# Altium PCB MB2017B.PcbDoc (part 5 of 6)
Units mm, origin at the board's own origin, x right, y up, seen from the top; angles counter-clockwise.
Board outline 148.19 x 169.19 mm, 4 copper layers (Top Layer, Mid Layer 1, Mid Layer 2, Bottom Layer), stack 1.498 mm thick; 458 components, 208 nets, 1223 pads, 6162 vias.
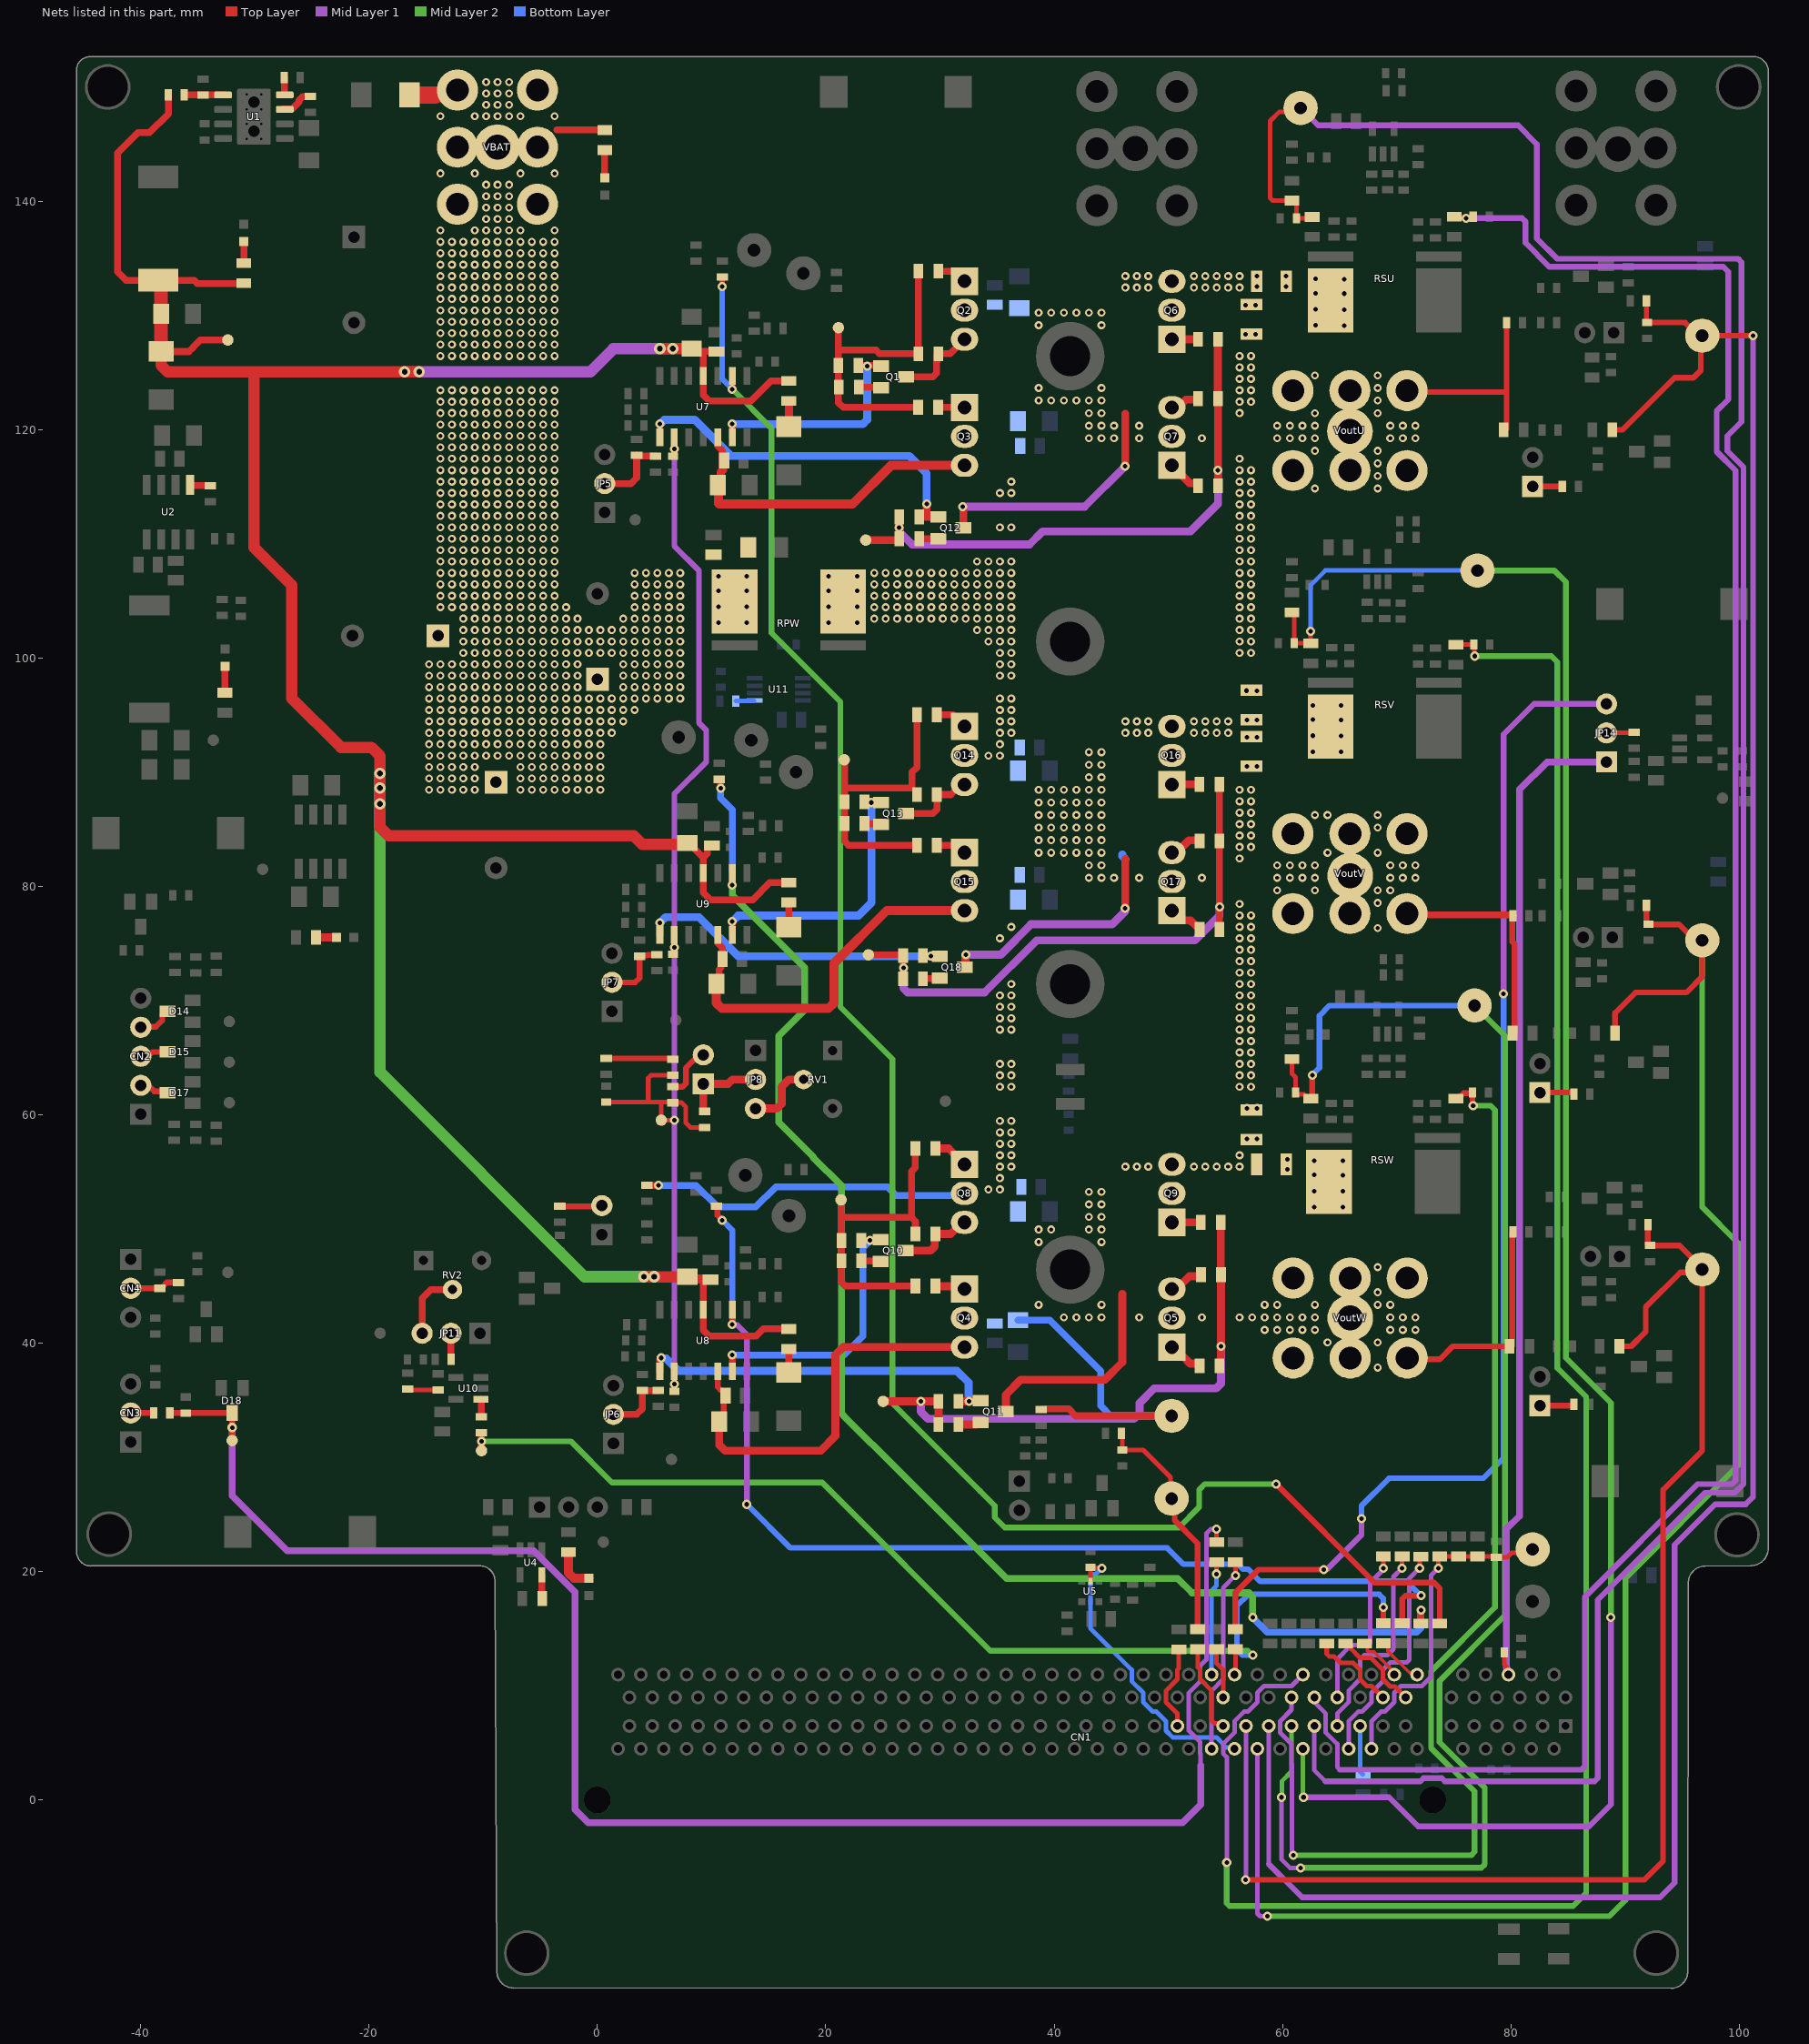
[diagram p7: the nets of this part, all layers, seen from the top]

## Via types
v1: diameter 0.7, hole 0.35, Top Layer to Bottom Layer, tented both sides, 5935 vias
v2: diameter 0.8, hole 0.4, Top Layer to Bottom Layer, tented both sides, 216 vias
v3: diameter 1, hole 0.5, Top Layer to Bottom Layer, tented both sides, 9 vias
v4: diameter 0.8, hole 0.4, Top Layer to Bottom Layer, 2 vias

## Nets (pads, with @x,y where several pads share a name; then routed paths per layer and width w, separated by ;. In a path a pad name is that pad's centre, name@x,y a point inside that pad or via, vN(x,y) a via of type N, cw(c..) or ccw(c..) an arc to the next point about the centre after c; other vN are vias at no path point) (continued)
NetCN1_A16: CN1.A16 Enable.1 R36.1 R39.1 R42.1 R44.2 | length 29
  Top Layer w0.4: v2(73.66,20.32) 73.66,21.223 R42.1@73.787,21.35 R39.1@75.438,21.35 R36.1@77.089,21.35 78.661,21.35 R44.2@78.74,21.271 79.691,21.271 80.068,21.648 81.592,21.648 Enable.1@81.915,21.971
  Mid Layer 1 w0.4: CN1.A16@67.8,4.5 67.8,6.914 68.636,7.75 68.964,7.75 69.8,8.586 69.8,9.414 70.386,10 72.214,10 73.025,10.811 73.025,19.685 v2(73.66,20.32)
NetCN1_A17: CN1.A17 R183.1 | length 4.4
  Bottom Layer w0.4: CN1.A17@66.8,6.5 66.8,2.483 67.025,2.258 R183.1@67.056,2.258
NetCN1_A18: CN1.A18 R43.1 | length 20.5
  Top Layer w0.4: v2(72.009,20.32) 72.009,21.209 R43.1@72.136,21.336
  Mid Layer 1 w0.4: CN1.A18@65.8,4.5 65.8,6.914 66.636,7.75 66.964,7.75 67.8,8.586 67.8,9.414 68.8,10.414 68.8,11.414 69.451,12.065 70.886,12.065 71.12,12.299 71.12,19.431 v2(72.009,20.32)
NetCN1_A19: CN1.A19 R45.1 | length 18.4
  Top Layer w0.4: v2(70.485,20.32) R45.1@70.485,21.35
  Mid Layer 1 w0.4: CN1.A19@64.8,6.5 64.8,7.586 65.8,8.586 65.8,9.586 66.8,10.586 66.8,11.414 66.8,12.317 67.183,12.7 69.215,12.7 69.723,13.208 69.723,19.558 v2(70.485,20.32)
NetCN1_A29: CN1.A29 R48.1 | length 8
  Top Layer w0.4: R48.1@52.578,13.222 52.578,11.636 52.8,11.414 52.8,10.586 53.8,9.586 53.8,6.965 54.034,6.731 54.353,6.731 54.584,6.5 CN1.A29@54.8,6.5
NetCN1_A30: CN1.A30 R50.1 | length 17.2
  Top Layer w0.4: v2(55.88,19.685) R50.1@55.88,20.842
  Mid Layer 1 w0.4: CN1.A30@53.8,4.5 53.8,9.586 54.8,10.586 54.8,18.605 v2(55.88,19.685)
NetCN1_A33: CN1.A33 R52.1 | length 7.6
  Top Layer w0.4: CN1.A33@50.8,6.5 50.8,7.586 49.8,8.586 49.8,9.586 50.8,10.586 50.8,11.414 50.927,11.541 R52.1@50.927,13.208
NetCN1_B12: CN1.B12 R33.2 | length 4.3
  Top Layer w0.3: R33.2@68.834,13.744 68.974,13.744 69.249,13.469 69.249,13.047 71.124,11.172 71.628,11.172 CN1.B12@71.8,11
NetCN1_B13: CN1.B13 R35.2 | length 7.8
  Top Layer w0.4: R35.2@65.532,13.73 65.757,13.73 65.982,13.505 65.982,13.28 66.816,12.446 67.768,12.446 68.8,11.414 68.8,10.586 69.433,9.953 69.847,9.953 CN1.B13@70.8,9
NetCN1_B14: CN1.B14 R38.2 | length 4.1
  Top Layer w0.3: R38.2@67.183,13.73 67.437,13.476 67.437,13.081 67.522,12.996 67.996,12.996 68.5,12.493 69.8,11.192 CN1.B14@69.8,11
NetCN1_B15: CN1.B15 R41.2 | length 7.9
  Top Layer w0.4: R41.2@63.881,13.73 63.881,12.807 64.115,12.573 64.54,12.573 65.091,12.023 66.191,12.023 66.8,11.414 66.8,10.586 67.386,10 67.8,10 CN1.B15@68.8,9
NetCN1_B19: CN1.B19 R46.2 | length 15.3
  Top Layer w0.4: CN1.B19@64.8,9 64.8,9.216 64.966,9.382 CN1.B19@64.966,9.4 ; v2(68.834,20.32) R46.2@68.834,21.35
  Mid Layer 1 w0.4: CN1.B19@64.8,9 64.8,12.349 66.04,13.589 67.457,13.589 67.691,13.823 67.691,19.05 68.634,19.993 68.634,20.012 68.834,20.212 v2(68.834,20.32)
NetCN1_B28: CN1.B28 R47.2 | length 2.3
  Top Layer w0.4: CN1.B28@55.8,11 55.88,11.08 R47.2@55.88,13.222
NetCN1_B29: CN1.B29 R49.2 | length 4.5
  Top Layer w0.4: R49.2@54.229,13.222 54.229,11.985 54.8,11.414 CN1.B29@54.8,9
NetCN1_B30: CN1.B30 R51.2 | length 10
  Top Layer w0.4: v2(54.229,19.812) R51.2@54.229,20.842
  Bottom Layer w0.4: CN1.B30@53.8,11 53.8,18.367 54.229,18.796 v2(54.229,19.812)
NetCN2_2: CN2.2 D17.3 | length 2.6
  Top Layer w0.5: CN2.2@-40.005,62.611 -39.747,62.353 -39.112,62.353 -38.833,62.074 -37.774,62.074 D17.3@-37.676,61.976
NetCN2_3: CN2.3 D15.3 | length 2.5
  Top Layer w0.5: CN2.3@-40.005,65.151 -39.747,65.409 -39.112,65.409 -38.989,65.532 D15.3@-37.676,65.532
NetCN2_4: CN2.4 D14.3 | length 3.2
  Top Layer w0.5: CN2.4@-40.005,67.691 -39.956,67.74 -38.686,67.74 -38.126,68.3 -38.126,68.838 -37.876,69.088 D14.3@-37.676,69.088
NetCN3_2: CN3.2 R160.1 | length 2
  Top Layer w0.5: CN3.2@-40.894,33.909 R160.1@-38.862,33.909
NetCN4_2: CN4.2 R173.1 R178.1 | length 4.4
  Top Layer w0.5: CN4.2@-40.894,44.831 R178.1@-38.354,44.831 -38.174,44.831 -38.104,44.901 -38.104,44.954 -37.719,45.339 R173.1@-36.703,45.339
NetD6_2: D6.2 R61.2 | length 2.3
  Top Layer w0.7: D6.2@16.764,120.298 R61.2@16.764,122.555
NetD7_2: D7.2 R91.2 | length 2
  Top Layer w0.6: D7.2@16.764,37.465 R91.2@16.764,39.511
NetD8_2: D8.2 R90.2 | length 2.2
  Top Layer w0.6: D8.2@16.764,76.454 R90.2@16.764,78.627
NetGHU_1: GHU.1 R59.2 R60.2 R62.1 R63.1 R64.2 | length 28.1
  Top Layer w0.6: GHU.1@21.105,128.967 21.105,127.127 ; R63.1@28.09,121.982 21.528,121.982 21.105,122.405 R59.2@21.105,125.665 21.105,127.127 ; R62.1@28.104,133.92 R64.2@28.104,126.681 24.703,126.681 24.384,127 21.232,127 21.105,127.127
NetGHV_1: GHV.1 R88.2 R89.2 R92.1 R93.1 R94.2 | length 26.1
  Top Layer w0.6: GHV.1@21.613,91.121 21.641,91.093 21.641,88.646 ; R93.1@27.977,83.628 21.992,83.628 21.641,83.979 R89.2@21.641,85.533 R88.2@21.641,87.438 21.641,88.646 ; R92.1@27.977,95.058 27.977,90.461 27.559,90.043 27.559,88.646 21.641,88.646
NetGHW_1: GHW.1 R65.1 R69.1 R75.1 R78.2 R86.2 | length 27.8
  Top Layer w0.6: GHW.1@21.336,52.578 21.336,51.054 ; R65.1@27.85,45.02 21.687,45.02 21.336,45.371 21.336,47.216 R78.2@21.364,47.244 R86.2@21.364,49.022 21.336,49.05 21.336,51.054 ; R69.1@27.85,49.592 27.85,50.703 27.499,51.054 ; R75.1@27.85,57.085 27.813,57.048 27.813,55.372 27.499,55.058 27.499,51.054 ; 21.336,51.054 27.499,51.054
NetGLU_1: GLU.1 R70.1 R71.1 R73.1 R83.2 R85.2 | length 50.9
  Top Layer w0.7: GLU.1@23.495,110.363 26.355,110.363 26.43,110.438 R85.2@26.43,110.49 v2(26.43,111.442) R83.2@26.43,112.395 ; R70.1@54.351,127.951 54.351,122.744 54.356,122.739 54.356,115.133 R71.1@54.365,115.124
  Mid Layer 1 w0.7: v2(26.43,111.442) 26.449,111.423 26.449,111.092 27.559,109.982 37.846,109.982 38.989,111.125 51.943,111.125 54.356,113.538 v2(54.356,116.459)
NetGLV_1: GLV.1 R97.1 R98.1 R100.1 R108.2 R109.2 | length 51
  Top Layer w0.6: GLV.1@23.729,74.037 26.706,74.037 R108.2@26.768,73.975 R109.2@26.768,71.943 ; R97.1@54.478,88.962 54.478,84.009 54.483,84.004 54.483,76.271 R98.1@54.492,76.262
  Mid Layer 1 w0.7: v2(26.797,72.898) 26.797,71.12 27.051,70.866 27.178,70.739 33.909,70.739 38.481,75.311 52.324,75.311 54.483,77.47 v2(54.483,78.232)
NetGLW_1: GLW.1 R66.1 R67.1 R76.1 R84.2 R87.2 | length 52
  Top Layer w0.7: GLW.1@25.019,34.925 v2(28.321,34.925) R87.2@29.873,34.925 29.873,32.907 R84.2@29.859,32.893 ; R66.1@54.492,38.035 54.567,38.11 54.567,38.485 54.605,38.523 54.605,39.612 54.61,39.617 54.61,46.031 54.605,46.036 R76.1@54.605,50.608
  Mid Layer 1 w0.7: v2(28.321,34.925) 28.321,34.036 28.956,33.401 46.99,33.401 47.498,33.909 47.498,34.798 48.768,36.068 54.2,36.068 54.61,36.478 v2(54.61,39.751)
NetJ1_1: J1.1 RSW.F2
  other v2: 65.278,51.943 62.783,51.957 65.278,53.34 62.783,53.354 65.278,54.737 62.783,54.751 60.452,55.245 65.278,56.007 62.783,56.021 60.452,56.134
NetJ2_1: J2.1 J5.1
  other v1: 56.247,100.484 57.247,100.484 56.247,101.484 57.247,101.484 56.247,102.484 57.247,102.484 56.247,103.484 57.247,103.484 56.247,104.484 57.247,104.484 56.247,105.484 57.247,105.484 56.247,106.484 57.247,106.484 56.247,107.484 57.247,107.484 56.247,108.484 57.247,108.484 56.247,109.484 57.247,109.484 56.247,110.484 57.247,110.484 56.247,111.484 57.247,111.484 56.247,112.484 57.247,112.484 56.247,113.484 57.247,113.484 56.247,114.484 57.247,114.484 56.247,115.484 57.247,115.484 56.247,116.484 57.247,116.484 56.247,117.484 56.247,121.484 56.247,122.484 57.247,122.484 56.247,123.484 57.247,123.484 56.247,124.484 57.247,124.484 56.247,125.484 57.247,125.484 56.247,126.484 57.247,126.484
  other v2: 57.785,97.155 56.859,97.175 56.769,128.397 57.658,128.397
NetJ3_2: J3.2 J6.1
  other v1: 56.247,62.484 57.247,62.484 56.247,63.484 57.247,63.484 56.247,64.484 57.247,64.484 56.247,65.484 57.247,65.484 56.247,66.484 57.247,66.484 56.247,67.484 57.247,67.484 56.247,68.484 57.247,68.484 56.247,69.484 57.247,69.484 56.247,70.484 57.247,70.484 56.247,71.484 57.247,71.484 56.247,72.484 57.247,72.484 56.247,73.484 57.247,73.484 56.247,74.484 57.247,74.484 56.247,75.484 57.247,75.484 56.247,76.484 57.247,76.484 56.247,77.484 57.247,77.484 56.247,78.484 56.247,82.484 56.247,83.484 57.247,83.484 56.247,84.484 57.247,84.484 56.247,85.484 57.247,85.484 56.247,86.484 57.247,86.484 56.247,87.484 57.247,87.484 56.247,88.484 57.247,88.484
  other v2: 56.896,60.579 57.785,60.579 56.896,90.551 57.785,90.551
NetJ4_1: J4.1 RSU.F2
  other v2: 65.405,129.159 62.91,129.173 65.405,130.556 62.91,130.57 65.405,131.953 62.91,131.967 60.325,132.588 65.405,133.223 62.91,133.237 60.325,133.477
NetJP2_1: JP2.1 R24.2 | length 2.6
  Top Layer w0.5: JP2.1@81.915,115.062 R24.2@84.517,115.062
NetJP3_1: JP3.1 R26.2 | length 3.1
  Top Layer w0.5: JP3.1@82.55,61.976 85.463,61.976 85.533,61.906 R26.2@85.533,61.849
NetJP4_1: JP4.1 R28.2 | length 3.1
  Top Layer w0.5: JP4.1@82.55,34.544 85.463,34.544 85.533,34.614 R28.2@85.533,34.671
NetJP5_2: JP5.2 R77.1 R81.2 | length 6.6
  Top Layer w0.6: JP5.2@0.635,115.316 2.921,115.316 3.429,115.824 R77.1@3.429,117.729 ; R77.1@3.429,117.791 R77.1@3.429,117.729 ; R81.2@5.08,117.729 R77.1@3.429,117.729
NetJP6_2: JP6.2 R79.1 R80.2 | length 5.7
  Top Layer w0.6: JP6.2@1.397,33.782 3.429,33.782 3.937,34.29 R79.1@3.937,35.876 5.331,35.876 R80.2@5.334,35.879
NetJP7_2: JP7.2 R102.1 R106.2 | length 6.1
  Top Layer w0.5: JP7.2@1.27,71.628 3.302,71.628 3.683,72.009 R102.1@3.683,73.911 3.753,73.981 4.385,73.981 4.445,74.041 R106.2@5.207,74.041
NetJP8_2: JP8.2 JP9.1 R110.2 | length 7.2
  Top Layer w0.7: R110.2@9.398,60.328 9.301,60.328 9.271,60.358 JP9.1@9.271,62.738 11.43,62.738 11.811,63.119 JP8.2@13.843,63.119
NetJP8_3: JP8.3 RV1.2 | length 6.1
  Top Layer w0.7: JP8.3@13.843,60.579 15.719,60.579 16.129,60.989 16.129,62.484 16.764,63.119 RV1.2@18.054,63.119
NetJP9_2: JP9.2 R111.1 | length 4.6
  Top Layer w0.5: R111.1@6.604,62.484 7.454,62.484 7.747,62.777 7.747,64.135 8.396,64.784 8.412,64.784 8.906,65.278 JP9.2@9.271,65.278
NetJP11_2: JP11.2 R119.2 | length 2.3
  Top Layer w0.6: R119.2@-12.827,38.608 JP11.2@-12.827,40.894
NetJP11_3: JP11.3 RV2.2 | length 6
  Top Layer w0.6: JP11.3@-15.367,40.894 -15.367,43.942 -14.585,44.724 RV2.2@-12.7,44.724
NetJP12_2: JP12.2 R125.2 | length 3.7
  Top Layer w0.5: R125.2@-3.302,52.008 0.319,52.008 JP12.2@0.381,52.07
NetJP14_2: JP14.2 R135.2 | length 2.4
  Top Layer w0.4: JP14.2@88.392,93.472 90.74,93.472 R135.2@90.805,93.537
NetLD1_1: LD1.1 R4.1 | length 1.9
  Top Layer w0.6: R4.1@-30.988,134.62 LD1.1@-30.988,136.525
NetLD2_1: LD2.1 R6.1 | length 2.4
  Top Layer w0.6: LD2.1@0.635,142.089 R6.1@0.635,144.526
NetLD3_1: LD3.1 R9.1 | length 2.3
  Top Layer w0.6: R9.1@-32.639,97 LD3.1@-32.639,99.314
NetLD4_1: LD4.1 R11.1 | length 1.8
  Top Layer w0.7: R11.1@-24.652,75.565 LD4.1@-22.86,75.565
NetLD5_1: LD5.1 R13.1 | length 3.8
  Top Layer w0.8: R13.1@-2.54,21.731 -2.54,19.9 -2.071,19.431 -0.774,19.431 LD5.1@-0.762,19.419
NetQ1_1: Q1.1 R59.1 U7.13 | length 19.8
  Top Layer w0.6: U7.13@11.811,119.347 v2(11.811,120.523) ; R59.1@22.855,125.665 24.765,125.665 Q1.1@24.831,125.599
  Bottom Layer w0.7: v2(11.811,120.523) 23.241,120.523 23.622,120.904 v2(23.622,125.603)
NetQ1_2: Q1.2 R60.1 | length 2
  Top Layer w0.6: R60.1@22.883,123.76 24.77,123.76 Q1.2@24.831,123.699
NetQ2_1: Q2.1 R62.2 | length 2.7
  Top Layer w0.6: R62.2@29.854,133.92 31.265,133.92 Q2.1@32.154,133.031
NetQ3_1: Q3.1 R63.2 | length 2.3
  Top Layer w0.6: R63.2@29.84,121.982 Q3.1@32.154,121.982
NetQ4_1: Q4.1 R65.2 | length 2.7
  Top Layer w0.6: Q4.1@31.9,45.02 Q4.1@32.154,44.766
  Top Layer w0.7: R65.2@29.6,45.02 Q4.1@31.9,45.02
NetQ5_1: Q5.1 R66.2 | length 3.2
  Top Layer w0.7: Q5.1@50.315,39.686 51.165,38.836 51.334,38.836 51.943,38.227 52.667,38.227 52.742,38.152 R66.2@52.742,38.035
NetQ6_1: Q6.1 R70.2 | length 2.3
  Top Layer w0.7: Q6.1@50.315,127.951 R70.2@52.601,127.951
NetQ7_1: Q7.1 R71.2 | length 3.1
  Top Layer w0.7: Q7.1@50.315,116.902 51.877,115.34 52.54,115.34 52.615,115.265 R71.2@52.615,115.124
NetQ8_1: Q8.1 R75.2 | length 3.1
  Top Layer w0.7: R75.2@29.6,57.085 30.757,57.085 Q8.1@32.154,55.688
NetQ9_1: Q9.1 R76.2 | length 2.5
  Top Layer w0.7: Q9.1@50.315,50.608 R76.2@52.855,50.608
NetQ10_1: Q10.1 R86.1 U8.13 | length 22.2
  Top Layer w0.6: U8.13@11.811,37.559 v2(11.811,38.989)
  Bottom Layer w0.6: v2(11.811,38.989) 21.59,38.989 23.241,40.64 23.241,48.387 v2(23.876,49.022)
NetQ10_2: Q10.2 R78.1 | length 1.7
  Top Layer w0.6: R78.1@23.114,47.244 23.145,47.213 24.777,47.213 Q10.2@24.808,47.183
NetQ11_1: Q11.1 R87.1 U8.8 | length 32.7
  Top Layer w0.6: U8.8@5.461,37.559 5.461,38.608 v2(5.588,38.735)
  Top Layer w0.7: R87.1@31.623,34.925 v2(32.567,34.925) 32.586,34.944 33.529,34.944 Q11.1@33.571,34.986
  Bottom Layer w0.6: v2(5.588,38.735) v2@5.626,38.697 ; v2@32.512,34.98 v2(32.567,34.925)
  Bottom Layer w0.7: v2@5.626,38.697 6.007,38.697 7.112,37.592 31.496,37.592 32.512,36.576 v2@32.512,34.98
NetQ11_2: Q11.2 R84.1 | length 2
  Top Layer w0.7: R84.1@31.609,32.893 33.178,32.893 33.371,33.086 Q11.2@33.571,33.086
NetQ12_1: Q12.1 R83.1 U7.8 | length 32.2
  Top Layer w0.5: U7.8@5.461,119.347 v2(5.461,120.523)
  Top Layer w0.7: R83.1@28.18,112.395 28.182,112.393 29.012,112.393 ; v2(28.829,113.538) 28.829,112.576 29.012,112.393 ; Q12.1@29.845,112.39 29.843,112.393 29.012,112.393
  Bottom Layer w0.7: v2(5.461,120.523) 5.488,120.523 5.869,120.904 8.509,120.904 11.684,117.729 27.305,117.729 28.829,116.205 v2(28.829,113.538)
NetQ12_2: Q12.2 R85.1 | length 1.7
  Top Layer w0.6: R85.1@28.18,110.49 Q12.2@29.845,110.49
NetQ13_1: Q13.1 R88.1 U9.13 | length 24.3
  Top Layer w0.6: U9.13@11.811,75.786 v2(11.811,76.962) ; R88.1@23.391,87.438 23.424,87.405 24.798,87.405 Q13.1@24.831,87.372
  Bottom Layer w0.7: v2(11.811,76.962) 12.319,77.47 22.86,77.47 24.003,78.613 v2(24.003,87.376)
NetQ13_2: Q13.2 R89.1 | length 1.5
  Top Layer w0.6: R89.1@23.391,85.533 23.422,85.502 24.8,85.502 Q13.2@24.831,85.472
NetQ14_1: Q14.1 R92.2 | length 2.8
  Top Layer w0.6: R92.2@29.727,95.058 31.138,95.058 Q14.1@32.154,94.042
NetQ15_1: Q15.1 R93.2 | length 2.7
  Top Layer w0.6: R93.2@29.727,83.628 31.519,83.628 Q15.1@32.154,82.993
NetQ16_1: Q16.1 R97.2 | length 2.4
  Top Layer w0.7: Q16.1@50.315,88.962 R97.2@52.728,88.962
NetQ17_1: Q17.1 R98.2 | length 3.2
  Top Layer w0.7: Q17.1@50.315,77.913 51.165,77.063 51.941,77.063 52.442,76.562 52.667,76.562 52.742,76.487 R98.2@52.742,76.262
NetQ18_1: Q18.1 R108.1 U9.8 | length 26.4
  Top Layer w0.6: U9.8@5.461,75.786 v2(5.461,76.835)
  Bottom Layer w0.7: v2(5.461,76.835) 5.969,77.343 8.89,77.343 12.319,73.914 v2(29.21,73.914)
NetQ18_2: Q18.2 R109.1 | length 1.5
  Top Layer w0.6: R109.1@28.518,71.943 28.551,71.976 29.939,71.976 Q18.2@29.972,72.009
NetR1_2: R1.2 U1.3 | length 3
  Top Layer w0.6: U1.3@-27.599,148.082 -27.549,148.132 -26.747,148.132 -26.162,148.717 -26.162,148.877 -25.831,149.208 -25.166,149.208 R1.2@-25.146,149.228
NetR2_1: R2.1 R5.2 U1.5 | length 3.6
  Top Layer w0.6: R2.1@-36.195,149.352 -34.547,149.352 R5.2@-34.544,149.349 -32.602,149.349 U1.5@-32.599,149.352
NetR3_2: R3.2 U1.4 | length 1.7
  Top Layer w0.6: U1.4@-27.599,149.352 -27.482,149.352 -27.432,149.402 -27.432,150.873 R3.2@-27.435,150.876
NetR7_2: R7.2 U2.5 | length 1.8
  Top Layer w0.6: U2.5@-35.687,115.189 -35.687,115.177 -35.637,115.127 R7.2@-33.909,115.127
NetR12_2: R12.2 U4.5 | length 2.1
  Top Layer w0.6: U4.5@-4.892,19.728 -4.892,17.705 R12.2@-4.84,17.653
NetR112_1: R112.1 R113.2 | length 5.9
  Top Layer w0.5: R113.2@0.762,64.962 6.542,64.962 R112.1@6.604,64.9
NetR121_1: R121.1 U10.1 | length 1.6
  Top Layer w0.6: U10.1@-10.203,35.118 -10.16,35.118 R121.1@-10.16,33.593
NetR126_1: R126.1 R129.2 | length 2.7
  Top Layer w0.4: R129.2@-16.637,36.003 -16.575,35.941 R126.1@-13.97,35.941
NetR128_1: R128.1 U11.5 | length 1.6
  Bottom Layer w0.4: R128.1@12.13,96.266 U11.5@13.709,96.266
OC_Bias: C45.2 C49.2 C69.2 C73.2 OC_Bias.1 R110.1 R111.2 R112.2 U7.9 U8.9 U9.9 | length 102.3
  Top Layer w0.4: C73.2@0.762,61.149 4.445,61.149 ; R112.2@6.604,63.5 4.699,63.5 4.445,63.246 4.445,61.149 ; v2(6.731,59.563) OC_Bias.1@5.588,59.563 5.588,61.149 ; R110.1@9.398,58.928 8.128,58.928 7.747,59.309 7.747,60.706 7.366,61.087 6.607,61.087 R111.2@6.604,61.084 6.539,61.149 5.588,61.149 ; 4.445,61.149 5.588,61.149
  Top Layer w0.5: C69.2@6.604,74.106 6.674,74.176 6.674,74.619 v2(6.731,74.676)
  Mid Layer 1 w0.5: v2(6.731,36.449) v2(6.731,59.563) v2(6.731,74.676) 6.731,88.138 9.525,90.932 9.525,93.726 8.89,94.361 8.89,107.696 6.731,109.855 v2(6.731,118.364)
Ocurrent1: R30.2 R82.2 U7.2 | length 168.4
  Top Layer w0.5: v2(10.922,132.588) R82.2@10.922,133.412 ; v2(11.811,123.571) U7.2@11.811,124.747 ; v2(59.436,27.686) 68.072,19.05 73.279,19.05 73.787,18.542 R30.2@73.787,15.466
  Mid Layer 2 w0.5: v2(11.811,123.571) 15.24,120.142 15.24,102.235 21.271,96.204 21.271,69.485 25.84,64.916 25.84,34.765 33.528,27.077 33.528,27.051 34.798,25.781 34.798,24.765 35.687,23.876 50.927,23.876 52.705,25.654 52.705,27.178 53.213,27.686 v2(59.436,27.686)
  Bottom Layer w0.5: v2(10.922,132.588) 10.922,124.46 v2(11.811,123.571)
Ocurrent2: R31.2 R107.2 U9.2 | length 125.6
  Top Layer w0.6: R107.2@10.668,89.408 10.775,89.408 10.795,89.388 v2(10.795,88.646) ; v2(11.811,80.137) U9.2@11.811,81.186 ; R31.2@72.136,15.466 v2(72.136,16.637)
  Mid Layer 2 w0.6: v2(11.811,80.137) 11.811,79.248 18.147,72.912 18.147,69.215 15.887,66.955 15.887,59.379 18.923,56.343 18.923,56.261 21.36,53.824 21.36,33.89 21.59,33.66 21.59,33.655 26.477,28.768 26.482,28.768 35.83,19.42 44.569,19.42 44.58,19.431 50.8,19.431 52.07,18.161 57.053,18.161 57.404,17.81 v2(57.404,16.002)
  Bottom Layer w0.6: v2(10.795,88.646) 10.795,87.757 11.811,86.741 v2(11.811,80.137) ; v2(57.404,16.002) 58.674,14.732 71.785,14.732 72.136,15.083 v2(72.136,16.637)
Ocurrent3: R32.2 R103.2 U8.2 | length 95
  Top Layer w0.5: R103.2@10.414,52.005 10.424,52.005 10.494,51.935 10.494,51.228 v2(10.922,50.8) ; v2(11.811,41.656) U8.2@11.811,42.959 ; R32.2@70.485,15.494 70.485,17.614 70.778,17.907 v2(72.136,17.907)
  Mid Layer 1 w0.5: v2(11.811,41.656) 11.868,41.599 12.249,41.599 13.081,40.767 v2(13.081,25.908)
  Bottom Layer w0.5: v2(10.922,50.8) 11.811,49.911 v2(11.811,41.656) ; v2(13.081,25.908) 16.891,22.098 49.911,22.098 51.347,20.662 56.105,20.662 56.527,20.24 56.976,20.24 58.039,19.177 70.866,19.177 v2(72.136,17.907)
OV_Vcc_Power: OV_Vcc.1 R33.1 R121.2 | length 97.9
  Top Layer w0.5: R33.1@68.834,15.494 v2(68.834,16.891)
  Top Layer w0.6: OV_Vcc.1@-10.16,30.607 R121.2@-10.16,32.193
  Mid Layer 2 w0.5: v2(-10.156,31.429) -2.346,31.429 1.27,27.813 19.685,27.813 34.417,13.081 56.961,13.081 57.342,12.7 v2(57.404,12.7)
  Bottom Layer w0.5: v2(57.404,12.7) 56.515,12.7 56.007,13.208 56.007,17.018 57.023,18.034 68.453,18.034 68.834,17.653 v2(68.834,16.891)
Ref_Current_6S: JP14.3 R47.1 | length 106.6
  Top Layer w0.5: R47.1@55.88,14.972 55.88,18.161 57.912,20.193 v2(63.627,20.193)
  Mid Layer 1 w0.5: v2(63.627,20.193) 63.684,20.25 63.938,20.25 66.929,23.241 v2(66.929,24.638) ; v2(79.375,70.612) 79.375,93.345 82.042,96.012 JP14.3@88.392,96.012
  Bottom Layer w0.5: v2(66.929,24.638) 66.929,25.781 69.342,28.194 77.597,28.194 79.375,29.972 v2(79.375,70.612)
ShuntU+: C95.1 CN1.A21 R145.2 R155.1 ShuntU+.1 | length 234.3
  Top Layer w0.4: ShuntU+.1@61.595,148.209 61.272,147.886 59.748,147.886 58.928,147.066 58.928,140.329 59.162,140.095 R155.1@60.833,140.095 60.989,140.095 61.214,139.87 C95.1@61.214,138.557 62.498,138.557 R145.2@62.611,138.67
  Mid Layer 1 w0.4: CN1.A21@62.8,6.5 62.8,2.605 63.754,1.651
  Mid Layer 1 w0.5: ShuntU+.1@61.595,148.209 63.119,146.685 80.645,146.685 82.296,145.034 82.296,136.779 84.074,135.001 99.91,135.001 100.203,134.708 100.203,120.709 98.972,119.478 98.972,118.172 100.395,116.749 100.395,27.689 99.63,26.924 97.028,26.924 87.63,17.526 87.63,1.944 87.337,1.651 74.226,1.651 73.949,1.928 72.351,1.928 72.074,1.651 63.754,1.651
ShuntU-: C104.1 CN1.B21 R159.1 | length 195.9
  Top Layer w0.5: R159.1@75.057,138.684 75.127,138.614 76.016,138.614 v2(76.073,138.557) 76.13,138.614 76.638,138.614 C104.1@76.708,138.684
  Mid Layer 1 w0.4: CN1.B21@62.8,9 62.953,8.847 62.953,8.421 63.8,7.574 63.8,5.914 64.8,4.914 64.8,2.891 65.024,2.667
  Mid Layer 1 w0.5: 65.024,2.667 86.194,2.667 86.487,2.96 86.487,17.78 96.393,27.686 99.402,27.686 99.695,27.979 99.695,116.459 98.044,118.11 98.044,121.666 99.06,122.682 99.06,133.858 98.617,134.301 83.377,134.301 81.28,136.398 81.28,138.264 80.987,138.557 v2(76.073,138.557)
ShuntV+: C109.1 CN1.A22 R161.2 R170.1 ShuntV+.1 | length 174.4
  Top Layer w0.4: R170.1@60.833,104.027 61.025,103.835 C109.1@61.025,101.346 62.456,101.346 R161.2@62.484,101.318 v2(62.484,102.362)
  Mid Layer 1 w0.5: v2(61.849,0.254) 69.342,0.254 71.882,-2.286 86.868,-2.286 88.773,-0.381 v2(88.773,16.002)
  Mid Layer 2 w0.4: CN1.A22@61.8,4.5 61.8,0.303 v2(61.849,0.254)
  Mid Layer 2 w0.5: ShuntV+.1@77.089,107.696 83.82,107.696 84.836,106.68 84.836,38.735 88.773,34.798 v2(88.773,16.002)
  Bottom Layer w0.4: v2(62.484,102.362) 62.484,106.426 63.754,107.696 ShuntV+.1@77.089,107.696
ShuntV-: C124.2 CN1.B22 R181.1 | length 175.7
  Top Layer w0.4: R181.1@75.184,101.205 76.756,101.205 C124.2@76.77,101.219 76.802,101.187 76.802,100.236 v2(76.835,100.203)
  Mid Layer 1 w0.4: v2@55.118,-5.422 55.118,3.768 54.8,4.086 54.8,4.914 55.8,5.914 55.8,6.914 56.636,7.75 56.964,7.75 57.8,8.586 57.8,9.414 58.386,10 60.8,10 CN1.B22@61.8,11
  Mid Layer 2 w0.5: v2(55.118,-5.461) 55.118,-9.037 55.352,-9.271 85.471,-9.271 86.614,-8.128 86.614,35.306 84.074,37.846 84.074,99.695 83.566,100.203 v2(76.835,100.203)
ShuntW+: C108.1 CN1.A23 R163.2 R172.1 ShuntW+.1 | length 136.8
  Top Layer w0.4: R172.1@60.833,64.897 60.833,63.627 61.152,63.308 C108.1@61.152,61.976 61.152,61.93 61.272,61.81 61.903,61.81 62.259,61.454 R163.2@62.484,61.454
  Top Layer w0.5: R163.2@62.484,61.454 62.611,61.581 v2(62.611,63.5)
  Mid Layer 1 w0.4: v2(59.933,0.254) 59.933,-5.196 60.661,-5.924 v2(61.605,-5.924)
  Mid Layer 2 w0.4: v2(59.933,0.254) 59.944,0.265 59.944,1.651 60.8,2.507 CN1.A23@60.8,6.5
  Mid Layer 2 w0.5: v2(61.605,-5.924) 77.431,-5.924 77.724,-5.631 77.724,1.091 73.75,5.065 73.75,10.435 79.502,16.187 79.502,66.929 ShuntW+.1@76.835,69.596
  Bottom Layer w0.5: v2(62.611,63.5) 63.246,64.135 63.246,68.707 64.135,69.596 ShuntW+.1@76.835,69.596
ShuntW-: C125.2 CN1.B23 R182.1 | length 104.5
  Top Layer w0.4: v2@76.643,60.898 v2(76.708,60.833)
  Top Layer w0.5: R182.1@75.184,61.454 75.359,61.629 75.599,61.629 75.882,61.912 76.579,61.912 C125.2@76.643,61.976 ; v2@76.643,60.898 C125.2@76.643,61.969
  Mid Layer 1 w0.4: CN1.B23@60.8,9 60.8,7.914 59.8,6.914 59.8,5.914 60.8,4.914 60.8,3.208 60.833,3.175 60.833,-4.416 60.883,-4.467 60.883,-4.749 v2(60.96,-4.826)
  Mid Layer 2 w0.5: v2(60.96,-4.826) 76.542,-4.826 76.835,-4.533 76.835,0.762 73.025,4.572 73.025,11.303 78.613,16.891 78.613,60.452 78.232,60.833 v2(76.708,60.833)
"Temp Sensor": C20.2 CN1.A28 U5.5 | length 26.7
  Top Layer w0.4: U5.5@43.18,19.188 C20.2@43.18,20.382 43.211,20.351 44.165,20.351 v2(44.196,20.32)
  Bottom Layer w0.4: v2(44.196,20.32) 44.17,20.32 43.662,19.812 43.414,19.812 43.18,19.578 43.18,15.034 46.8,11.414 46.8,10.414 47.8,9.414 47.8,8.586 48.636,7.75 48.964,7.75 49.8,6.914 49.8,6.086 50.386,5.5 51.321,5.5 52.257,5.5 53.3,5.5 54.214,5.5 54.8,4.914 54.8,4.866 55.034,4.631 55.669,4.631 CN1.A28@55.8,4.5
Throttle: C107.1 D18.3 R51.1 R160.2 Throttle.1 | length 149.4
  Top Layer w0.4: R51.1@54.229,22.592 v2(54.229,23.749)
  Top Layer w0.5: R160.2@-37.462,33.909 C107.1@-36.068,33.909 D18.3@-32.004,33.909 v2(-32.004,32.639) Throttle.1@-32.004,31.496
  Mid Layer 1 w0.4: 52.832,3.048 52.832,4.054 52.8,4.086 52.8,5.086 51.8,6.086 51.8,9.414 52.8,10.414 52.8,10.586 52.8,11.779 53.34,12.319 53.34,23.368 53.721,23.749 v2(54.229,23.749)
  Mid Layer 1 w0.6: v2(-32.004,32.639) -32.004,26.67 -27.178,21.844 -5.588,21.844 -1.98,18.236 -1.98,-0.819 -0.821,-1.978 51.235,-1.978 52.832,-0.381 52.832,3.048
U: J2.2 J4.2 Q6.3 Q7.3 Q12.3 R73.2 | length 24.8
  Top Layer w0.7: v2(32.004,113.284) 32.045,113.243 Q12.3@32.045,111.44 ; v2(46.228,116.84) 46.228,121.424 ; Q7.3@50.315,121.982 50.862,121.982 51.55,122.67 52.541,122.67 R73.2@52.615,122.744
  Mid Layer 1 w0.7: v2(32.004,113.284) 42.672,113.284 v2(46.228,116.84)
  other v1: 46.247,132.484 47.247,132.484 48.247,132.484 52.247,132.484 53.247,132.484 54.247,132.484 55.247,132.484 56.247,132.484 46.247,133.484 47.247,133.484 48.247,133.484 52.247,133.484 53.247,133.484 54.247,133.484 55.247,133.484 56.247,133.484
  other v2: 56.769,130.937 57.658,130.937 57.785,132.588 57.785,133.477
V: J5.2 J6.2 Q16.3 Q17.3 Q18.3 R100.2 RSV.F2 | length 24.6
  Top Layer w0.7: Q18.3@32.172,72.959 32.239,73.026 32.239,74.022 v2(32.258,74.041) ; v2(46.228,78.105) 46.228,82.423 ; Q17.3@50.315,82.993 50.735,82.993 51.816,84.074 52.677,84.074 R100.2@52.742,84.009
  Mid Layer 1 w0.7: v2(32.258,74.041) 35.306,74.041 37.973,76.708 45.085,76.708 46.228,77.851 v2(46.228,78.105)
  Bottom Layer w0.7: 45.974,82.804 45.974,82.677 46.228,82.423
  other v1: 46.247,93.484 47.247,93.484 48.247,93.484 52.247,93.484 53.247,93.484 54.247,93.484 55.247,93.484 46.247,94.484 47.247,94.484 48.247,94.484 52.247,94.484 53.247,94.484 54.247,94.484 55.247,94.484
  other v2: 65.151,91.821 62.656,91.835 56.896,93.091 57.785,93.091 65.151,93.218 62.656,93.232 56.896,94.615 57.785,94.615 65.151,94.615 62.656,94.629 65.151,95.885 62.656,95.899
Vbat: C50.1 C51.1 C54.1 C55.1 C56.1 D1.2 pad.5@-8.763,144.78 R6.2 RPW.F1 VBAT.1 | length 7
  Top Layer w0.6: -3.556,146.304 -3.528,146.276 R6.2@0.635,146.276 ; C51.1@13.081,109.22 13.127,109.22 13.208,109.301 C51.1@13.208,109.728
  Top Layer w1.5: D1.2@-16.481,149.352 -14.224,149.352
  other v1: -14.753,88.484 -13.753,88.484 -12.753,88.484 -11.753,88.484 -10.753,88.484 -6.753,88.484 -5.753,88.484 -4.753,88.484 -3.753,88.484 -2.753,88.484 -1.753,88.484 -0.753,88.484 0.247,88.484 -14.753,89.484 -13.753,89.484 -12.753,89.484 -11.753,89.484 -10.753,89.484 -6.753,89.484 -5.753,89.484 -4.753,89.484 -3.753,89.484 -2.753,89.484 -1.753,89.484 -0.753,89.484 0.247,89.484 -14.753,90.484 -13.753,90.484 -12.753,90.484 -11.753,90.484 -10.753,90.484 -6.753,90.484 -5.753,90.484 -4.753,90.484 -3.753,90.484 -2.753,90.484 -1.753,90.484 -0.753,90.484 0.247,90.484 -14.753,91.484 -13.753,91.484 -12.753,91.484 -11.753,91.484 -10.753,91.484 -9.753,91.484 -8.753,91.484 -7.753,91.484 -6.753,91.484 -5.753,91.484 -4.753,91.484 -3.753,91.484 -2.753,91.484 -1.753,91.484 -0.753,91.484 0.247,91.484 -14.753,92.484 -13.753,92.484 -12.753,92.484 -11.753,92.484 -10.753,92.484 -9.753,92.484 -8.753,92.484 -7.753,92.484 -6.753,92.484 -5.753,92.484 -4.753,92.484 -3.753,92.484 -2.753,92.484 -1.753,92.484 -0.753,92.484 0.247,92.484 -14.753,93.484 -13.753,93.484 -12.753,93.484 -11.753,93.484 -10.753,93.484 -9.753,93.484 -8.753,93.484 -7.753,93.484 -6.753,93.484 -5.753,93.484 -4.753,93.484 -3.753,93.484 -2.753,93.484 -1.753,93.484 -0.753,93.484 0.247,93.484 1.247,93.484 -14.753,94.484 -13.753,94.484 -12.753,94.484 -11.753,94.484 -10.753,94.484 -9.753,94.484 -8.753,94.484 -7.753,94.484 -6.753,94.484 -5.753,94.484 -4.753,94.484 -3.753,94.484 -2.753,94.484 -1.753,94.484 -0.753,94.484 0.247,94.484 1.247,94.484 2.247,94.484 -14.753,95.484 -13.753,95.484 -12.753,95.484 -11.753,95.484 -10.753,95.484 -9.753,95.484 -8.753,95.484 -7.753,95.484 -6.753,95.484 -5.753,95.484 -4.753,95.484 -3.753,95.484 -2.753,95.484 -1.753,95.484 -0.753,95.484 0.247,95.484 1.247,95.484 2.247,95.484 3.247,95.484 -14.753,96.484 -13.753,96.484 -12.753,96.484 -11.753,96.484 -10.753,96.484 -9.753,96.484 -8.753,96.484 -7.753,96.484 -6.753,96.484 -5.753,96.484 -4.753,96.484 -3.753,96.484 -2.753,96.484 -1.753,96.484 -0.753,96.484 0.247,96.484 1.247,96.484 2.247,96.484 3.247,96.484 4.247,96.484 5.247,96.484 6.247,96.484 7.247,96.484 -14.753,97.484 -13.753,97.484 -12.753,97.484 -11.753,97.484 -10.753,97.484 -9.753,97.484 -8.753,97.484 -7.753,97.484 -6.753,97.484 -5.753,97.484 -4.753,97.484 -3.753,97.484 -2.753,97.484 -1.753,97.484 2.247,97.484 3.247,97.484 4.247,97.484 5.247,97.484 6.247,97.484 7.247,97.484 -14.753,98.484 -13.753,98.484 -12.753,98.484 -11.753,98.484 -10.753,98.484 -9.753,98.484 -8.753,98.484 -7.753,98.484 -6.753,98.484 -5.753,98.484 -4.753,98.484 -3.753,98.484 -2.753,98.484 -1.753,98.484 2.247,98.484 3.247,98.484 4.247,98.484 5.247,98.484 6.247,98.484 7.247,98.484 -14.753,99.484 -13.753,99.484 -12.753,99.484 -11.753,99.484 -10.753,99.484 -9.753,99.484 -8.753,99.484 -7.753,99.484 -6.753,99.484 -5.753,99.484 -4.753,99.484 -3.753,99.484 -2.753,99.484 -1.753,99.484 2.247,99.484 3.247,99.484 4.247,99.484 5.247,99.484 6.247,99.484 7.247,99.484 -11.753,100.484 -10.753,100.484 -9.753,100.484 -8.753,100.484 -7.753,100.484 -6.753,100.484 -5.753,100.484 -4.753,100.484 -3.753,100.484 -2.753,100.484 -1.753,100.484 -0.753,100.484 0.247,100.484 1.247,100.484 2.247,100.484 3.247,100.484 4.247,100.484 5.247,100.484 6.247,100.484 7.247,100.484 -11.753,101.484 -10.753,101.484 -9.753,101.484 -8.753,101.484 -7.753,101.484 -6.753,101.484 -5.753,101.484 -4.753,101.484 -3.753,101.484 -2.753,101.484 -1.753,101.484 -0.753,101.484 0.247,101.484 1.247,101.484 2.247,101.484 3.247,101.484 4.247,101.484 5.247,101.484 6.247,101.484 7.247,101.484 -11.753,102.484 -10.753,102.484 -9.753,102.484 -8.753,102.484 -7.753,102.484 -6.753,102.484 -5.753,102.484 -4.753,102.484 -3.753,102.484 -2.753,102.484 -1.753,102.484 -0.753,102.484 0.247,102.484 1.247,102.484 2.247,102.484 3.247,102.484 4.247,102.484 5.247,102.484 6.247,102.484 7.247,102.484 -11.753,103.484 -10.753,103.484 -9.753,103.484 -8.753,103.484 -7.753,103.484 -6.753,103.484 -5.753,103.484 -4.753,103.484 -3.753,103.484 -2.753,103.484 -1.753,103.484 2.247,103.484 3.247,103.484 4.247,103.484 5.247,103.484 6.247,103.484 7.247,103.484 -13.753,104.484 -12.753,104.484 -11.753,104.484 -10.753,104.484 -9.753,104.484 -8.753,104.484 -7.753,104.484 -6.753,104.484 -5.753,104.484 -4.753,104.484 -3.753,104.484 -2.753,104.484 3.247,104.484 4.247,104.484 5.247,104.484 6.247,104.484 7.247,104.484 -13.753,105.484 -12.753,105.484 -11.753,105.484 -10.753,105.484 -9.753,105.484 -8.753,105.484 -7.753,105.484 -6.753,105.484 -5.753,105.484 -4.753,105.484 -3.753,105.484 3.247,105.484 4.247,105.484 5.247,105.484 6.247,105.484 7.247,105.484 -13.753,106.484 -12.753,106.484 -11.753,106.484 -10.753,106.484 -9.753,106.484 -8.753,106.484 -7.753,106.484 -6.753,106.484 -5.753,106.484 -4.753,106.484 -3.753,106.484 3.247,106.484 4.247,106.484 5.247,106.484 6.247,106.484 7.247,106.484 -13.753,107.484 -12.753,107.484 -11.753,107.484 -10.753,107.484 -9.753,107.484 -8.753,107.484 -7.753,107.484 -6.753,107.484 -5.753,107.484 -4.753,107.484 -3.753,107.484 3.247,107.484 4.247,107.484 5.247,107.484 6.247,107.484 7.247,107.484 -13.753,108.484 -12.753,108.484 -11.753,108.484 -10.753,108.484 -9.753,108.484 -8.753,108.484 -7.753,108.484 -6.753,108.484 -5.753,108.484 -4.753,108.484 -3.753,108.484 -13.753,109.484 -12.753,109.484 -11.753,109.484 -10.753,109.484 -9.753,109.484 -8.753,109.484 -7.753,109.484 -6.753,109.484 -5.753,109.484 -4.753,109.484 -3.753,109.484 -13.753,110.484 -12.753,110.484 -11.753,110.484 -10.753,110.484 -9.753,110.484 -8.753,110.484 -7.753,110.484 -6.753,110.484 -5.753,110.484 -4.753,110.484 -3.753,110.484 -13.753,111.484 -12.753,111.484 -11.753,111.484 -10.753,111.484 -9.753,111.484 -8.753,111.484 -7.753,111.484 -6.753,111.484 -5.753,111.484 -4.753,111.484 -3.753,111.484 -13.753,112.484 -12.753,112.484 -11.753,112.484 -10.753,112.484 -9.753,112.484 -8.753,112.484 -7.753,112.484 -6.753,112.484 -5.753,112.484 -4.753,112.484 -3.753,112.484 -13.753,113.484 -12.753,113.484 -11.753,113.484 -10.753,113.484 -9.753,113.484 -8.753,113.484 -7.753,113.484 -6.753,113.484 -5.753,113.484 -4.753,113.484 -3.753,113.484 -13.753,114.484 -12.753,114.484 -11.753,114.484 -10.753,114.484 -9.753,114.484 -8.753,114.484 -7.753,114.484 -6.753,114.484 -5.753,114.484 -4.753,114.484 -3.753,114.484 -13.753,115.484 -12.753,115.484 -11.753,115.484 -10.753,115.484 -9.753,115.484 -8.753,115.484 -7.753,115.484 -6.753,115.484 -5.753,115.484 -4.753,115.484 -3.753,115.484 -13.753,116.484 -12.753,116.484 -11.753,116.484 -10.753,116.484 -9.753,116.484 -8.753,116.484 -7.753,116.484 -6.753,116.484 -5.753,116.484 -4.753,116.484 -3.753,116.484 -13.753,117.484 -12.753,117.484 -11.753,117.484 -10.753,117.484 -9.753,117.484 -8.753,117.484 -7.753,117.484 -6.753,117.484 -5.753,117.484 -4.753,117.484 -3.753,117.484 -13.753,118.484 -12.753,118.484 -11.753,118.484 -10.753,118.484 -9.753,118.484 -8.753,118.484 -7.753,118.484 -6.753,118.484 -5.753,118.484 -4.753,118.484 -3.753,118.484 -13.753,119.484 -12.753,119.484 -11.753,119.484 -10.753,119.484 -9.753,119.484 -8.753,119.484 -7.753,119.484 -6.753,119.484 -5.753,119.484 -4.753,119.484 -3.753,119.484 -13.753,120.484 -12.753,120.484 -11.753,120.484 -10.753,120.484 -9.753,120.484 -8.753,120.484 -7.753,120.484 -6.753,120.484 -5.753,120.484 -4.753,120.484 -3.753,120.484 -13.753,121.484 -12.753,121.484 -11.753,121.484 -10.753,121.484 -9.753,121.484 -8.753,121.484 -7.753,121.484 -6.753,121.484 -5.753,121.484 -4.753,121.484 -3.753,121.484 -13.753,122.484 -12.753,122.484 -11.753,122.484 -10.753,122.484 -9.753,122.484 -8.753,122.484 -7.753,122.484 -6.753,122.484 -5.753,122.484 -4.753,122.484 -3.753,122.484 -13.753,123.484 -12.753,123.484 -11.753,123.484 -10.753,123.484 -9.753,123.484 -8.753,123.484 -7.753,123.484 -6.753,123.484 -5.753,123.484 -4.753,123.484 -3.753,123.484 -13.753,126.484 -12.753,126.484 -11.753,126.484 -10.753,126.484 -9.753,126.484 -8.753,126.484 -7.753,126.484 -6.753,126.484 -5.753,126.484 -4.753,126.484 -3.753,126.484 -13.753,127.484 -12.753,127.484 -11.753,127.484 -10.753,127.484 -9.753,127.484 -8.753,127.484 -7.753,127.484 -6.753,127.484 -5.753,127.484 -4.753,127.484 -3.753,127.484 -13.753,128.484 -12.753,128.484 -11.753,128.484 -10.753,128.484 -9.753,128.484 -8.753,128.484 -7.753,128.484 -6.753,128.484 -5.753,128.484 -4.753,128.484 -3.753,128.484 -13.753,129.484 -12.753,129.484 -11.753,129.484 -10.753,129.484 -9.753,129.484 -8.753,129.484 -7.753,129.484 -6.753,129.484 -5.753,129.484 -4.753,129.484 -3.753,129.484 -13.753,130.484 -12.753,130.484 -11.753,130.484 -10.753,130.484 -9.753,130.484 -8.753,130.484 -7.753,130.484 -6.753,130.484 -5.753,130.484 -4.753,130.484 -3.753,130.484 -13.753,131.484 -12.753,131.484 -11.753,131.484 -10.753,131.484 -9.753,131.484 -8.753,131.484 -7.753,131.484 -6.753,131.484 -5.753,131.484 -4.753,131.484 -3.753,131.484 -13.753,132.484 -12.753,132.484 -11.753,132.484 -10.753,132.484 -9.753,132.484 -8.753,132.484 -7.753,132.484 -6.753,132.484 -5.753,132.484 -4.753,132.484 -3.753,132.484 -13.753,133.484 -12.753,133.484 -11.753,133.484 -10.753,133.484 -9.753,133.484 -8.753,133.484 -7.753,133.484 -6.753,133.484 -5.753,133.484 -4.753,133.484 -3.753,133.484 -13.753,134.484 -12.753,134.484 -11.753,134.484 -10.753,134.484 -9.753,134.484 -8.753,134.484 -7.753,134.484 -6.753,134.484 -5.753,134.484 -4.753,134.484 -3.753,134.484 -13.753,135.484 -12.753,135.484 -11.753,135.484 -10.753,135.484 -9.753,135.484 -8.753,135.484 -7.753,135.484 -6.753,135.484 -5.753,135.484 -4.753,135.484 -3.753,135.484 -13.753,136.484 -12.753,136.484 -11.753,136.484 -10.753,136.484 -9.753,136.484 -8.753,136.484 -7.753,136.484 -6.753,136.484 -5.753,136.484 -4.753,136.484 -3.753,136.484 -13.753,137.484 -10.753,137.484 -9.753,137.484 -8.753,137.484 -7.753,137.484 -6.753,137.484 -3.753,137.484 -9.753,138.484 -8.753,138.484 -7.753,138.484 -9.753,139.484 -8.753,139.484 -7.753,139.484 -9.753,140.484 -8.753,140.484 -7.753,140.484 -9.753,141.484 -8.753,141.484 -7.753,141.484 -13.753,142.484 -10.753,142.484 -6.753,142.484 -3.753,142.484 -13.753,147.484 -10.753,147.484 -9.753,147.484 -8.753,147.484 -7.753,147.484 -6.753,147.484 -3.753,147.484 -9.753,148.484 -8.753,148.484 -7.753,148.484 -9.753,149.484 -8.753,149.484 -7.753,149.484 -9.753,150.484 -8.753,150.484 -7.753,150.484
  other v2: 13.081,103.124 10.586,103.138 13.081,104.521 10.586,104.535 13.081,105.918 10.586,105.932 13.081,107.188 10.586,107.202
Vcc_Gate: 12V5.1 C4.2 C36.2 C38.2 C59.2 C60.2 C65.2 C70.2 D2.2 L1.2 R2.2 R4.2 R61.1 R90.1 R91.1 U7.4 U8.4 U9.4 | length 271.9
  Top Layer w0.6: D2.2@-38.227,126.902 -38.198,126.873 -35.784,126.873 -35.433,127.224 -35.433,127.254 -34.798,127.889 12V5.1@-32.385,127.889 ; R2.2@-37.595,149.352 -37.595,147.698 -39.243,146.05 -40.259,146.05 -42.037,144.272 -42.037,133.858 -41.292,133.113 L1.2@-38.481,133.113 -35.323,133.113 -35.052,132.842 -31.016,132.842 R4.2@-30.988,132.87 ; C59.2@7.753,83.693 8.185,83.693 8.464,83.414 8.464,83.357 9.271,82.55 ; C36.2@8.255,127.127 8.504,126.878 9.271,126.878 ; 9.144,45.643 9.271,45.516 U8.4@9.271,42.959 9.271,41.148 9.779,40.64 13.873,40.64 14.508,41.275 16.75,41.275 R91.1@16.764,41.261 ; C38.2@10.014,126.723 10.164,126.873 C38.2@10.414,126.873 10.409,126.878 9.271,126.878 ; C60.2@10.033,83.605 9.783,83.605 9.633,83.455 9.633,82.912 9.271,82.55 ; R90.1@16.764,80.377 15.099,80.377 13.589,78.867 9.906,78.867 9.271,79.502 U9.4@9.271,81.186 9.271,82.55 ; R61.1@16.764,124.305 15.212,124.305 13.462,122.555 9.779,122.555 9.271,123.063 U7.4@9.271,124.747 9.271,126.878
  Top Layer w0.8: C70.2@7.874,45.844 8.075,45.643 9.144,45.643
  Top Layer w1: D2.2@-38.227,126.902 -38.227,125.681 -37.641,125.095 -30.099,125.095 ; v3(-15.621,125.095) -30.099,125.095 ; v3(4.064,45.847) 4.067,45.844 C70.2@7.874,45.844 ; v3(5.461,127.127) v3(6.604,127.127) C36.2@8.255,127.127 ; C59.2@7.753,83.693 3.937,83.693 3.175,84.455 -18.288,84.455 -19.05,85.217 v3(-19.05,87.249) v3(-19.05,88.646) v3(-19.05,89.916) -19.05,91.44 -19.812,92.202 -22.479,92.202 -26.797,96.52 -26.797,106.426 -30.099,109.728 -30.099,125.095
  Top Layer w1.2: L1.2@-38.481,133.113 -38.227,132.859 C4.2@-38.227,130.175 D2.2@-38.227,126.902
  Mid Layer 1 w1: v3(-16.891,125.095) v3(-15.621,125.095) -0.635,125.095 1.397,127.127 v3(5.461,127.127) v3(6.604,127.127)
  Mid Layer 2 w1: v3(-19.05,89.916) v3(-19.05,88.646) v3(-19.05,87.249) -19.05,63.754 -1.143,45.847 v3(4.064,45.847) v3(4.953,45.847)
Vcc_power: C29.1 C30.1 C31.1 C32.1 C33.1 C34.1 C35.1 C37.1 C52.1 C53.1 C57.1 C58.1 Q2.2 Q3.2 Q4.2 Q8.2 Q14.2 Q15.2 R120.2 R143.2 RPW.F2 Vcc_power.1 | length 60.2
  Top Layer w0.6: R120.2@4.318,53.848 v2(5.334,53.848) ; R143.2@38.862,34.228 38.882,34.248 39.278,34.248 39.32,34.29 41.275,34.29 41.91,33.655 Vcc_power.1@50.292,33.655
  Bottom Layer w0.6: v2(5.334,53.848) 8.636,53.848 10.541,51.943 13.843,51.943 15.621,53.721 25.4,53.721 26.162,52.959 31.965,52.959 Q8.2@32.154,53.148 ; C35.1@36.83,42.04 39.621,42.04 44.069,37.592 44.069,34.544 44.958,33.655 Vcc_power.1@50.292,33.655
  other v1: 34.247,53.484 35.247,53.484 35.247,54.484 35.247,55.484 36.247,55.484 35.247,56.484 36.247,56.484 35.247,57.484 36.247,57.484 35.247,58.484 36.247,58.484 35.247,59.484 36.247,59.484 35.247,62.484 36.247,62.484 35.247,63.484 36.247,63.484 35.247,64.484 36.247,64.484 35.247,67.484 36.247,67.484 35.247,68.484 36.247,68.484 35.247,69.484 36.247,69.484 35.247,70.484 36.247,70.484 36.247,71.484 35.247,75.484 36.247,76.484 34.247,91.484 35.247,91.484 35.247,92.484 35.247,93.484 36.247,93.484 35.247,94.484 36.247,94.484 35.247,95.484 36.247,95.484 35.247,96.484 36.247,96.484 35.247,98.484 36.247,98.484 35.247,99.484 36.247,99.484 35.247,100.484 36.247,100.484 34.247,101.484 35.247,101.484 36.247,101.484 33.247,102.484 34.247,102.484 35.247,102.484 36.247,102.484 24.247,103.484 25.247,103.484 26.247,103.484 27.247,103.484 28.247,103.484 29.247,103.484 30.247,103.484 31.247,103.484 32.247,103.484 33.247,103.484 34.247,103.484 35.247,103.484 36.247,103.484 24.247,104.484 25.247,104.484 26.247,104.484 27.247,104.484 28.247,104.484 29.247,104.484 30.247,104.484 31.247,104.484 32.247,104.484 33.247,104.484 34.247,104.484 35.247,104.484 36.247,104.484 24.247,105.484 25.247,105.484 26.247,105.484 27.247,105.484 28.247,105.484 29.247,105.484 30.247,105.484 31.247,105.484 32.247,105.484 33.247,105.484 34.247,105.484 35.247,105.484 36.247,105.484 24.247,106.484 25.247,106.484 26.247,106.484 27.247,106.484 28.247,106.484 29.247,106.484 30.247,106.484 31.247,106.484 32.247,106.484 33.247,106.484 34.247,106.484 35.247,106.484 36.247,106.484 24.247,107.484 25.247,107.484 26.247,107.484 27.247,107.484 28.247,107.484 29.247,107.484 30.247,107.484 31.247,107.484 32.247,107.484 33.247,107.484 34.247,107.484 35.247,107.484 36.247,107.484 33.247,108.484 34.247,108.484 35.247,108.484 36.247,108.484 35.247,111.484 36.247,111.484 35.247,114.484 36.247,114.484 36.247,115.484
  other v2: 22.733,103.124 20.238,103.138 22.733,104.521 20.238,104.535 22.733,105.918 20.238,105.932 22.733,107.188 20.238,107.202
Vcc_Pw: C99.2 R48.2 R144.2 Vcc_PW.1 | length 21
  Top Layer w0.4: R144.2@45.912,32.131 45.974,32.069 C99.2@45.974,30.672 47.814,30.672 50.204,28.282 50.204,26.504 Vcc_PW.1@50.292,26.416
  Top Layer w0.5: Vcc_PW.1@50.292,26.416 50.557,26.151 50.557,24.5 52.578,22.479 R48.2@52.578,14.972
VoutU: C39.1 C40.1 pad.5@65.913,119.888 Q1.3 Q2.3 Q3.3 Q6.2 Q7.2 R18.2 R64.1 R115.2 U7.12 VoutU.1 | length 54.8
  Top Layer w0.5: VoutU.1@70.833,123.332 79.614,123.332 79.629,123.317 ; R18.2@79.564,120.015 79.629,120.08 79.629,123.317 ; R115.2@79.629,129.413 79.629,123.317
  Top Layer w0.6: U7.12@10.541,119.347 10.541,118.618 10.938,118.221 10.938,117.298 C39.1@10.988,117.248 ; Q1.3@27.031,124.649 29.367,124.649 29.718,125 29.718,125.98 29.729,125.991 29.729,126.556 R64.1@29.854,126.681 30.884,126.681 Q2.3@32.154,127.951
  Top Layer w0.7: C40.1@10.538,115.189 10.795,115.446 10.795,116.332 10.988,116.525 C39.1@10.988,117.248
  Top Layer w0.8: C40.1@10.538,115.189 10.599,115.128 10.599,113.568 10.629,113.538 22.352,113.538 25.716,116.902 Q3.3@32.154,116.902
  other v1: 62.847,114.884 68.347,114.884 68.347,115.984 68.347,117.084 62.847,118.184 68.347,118.184 43.047,119.284 44.147,119.284 45.247,119.284 47.447,119.284 52.947,119.284 59.547,119.284 60.647,119.284 61.747,119.284 62.847,119.284 69.447,119.284 70.547,119.284 71.647,119.284 43.047,120.384 44.147,120.384 45.247,120.384 47.447,120.384 59.547,120.384 60.647,120.384 61.747,120.384 62.847,120.384 69.447,120.384 70.547,120.384 71.647,120.384 43.047,121.484 44.147,121.484 62.847,121.484 68.347,121.484 38.647,122.584 39.747,122.584 40.847,122.584 41.947,122.584 43.047,122.584 44.147,122.584 68.347,122.584 38.647,123.684 44.147,123.684 68.347,123.684 62.847,124.784 68.347,124.784 38.647,129.184 44.147,129.184 38.647,130.284 39.747,130.284 40.847,130.284 41.947,130.284 43.047,130.284 44.147,130.284
VoutV: C61.1 C62.1 pad.5@65.936,80.961 Q13.3 Q14.3 Q15.3 Q16.2 Q17.2 R19.2 R94.1 R123.2 U9.12 VoutV.1 | length 60.5
  Top Layer w0.5: R123.2@80.199,77.47 80.137,77.408 80.137,75.184 80.326,74.995 R19.2@80.326,67.183
  Top Layer w0.6: C62.1@10.414,71.501 10.668,71.755 10.668,72.771 10.811,72.914 10.811,73.51 C61.1@10.961,73.66 10.922,73.699 10.922,74.676 10.541,75.057 U9.12@10.541,75.786 ; Q13.3@27.031,86.422 29.376,86.422 29.727,86.773 R94.1@29.727,88.073 30.956,88.073 31.845,88.962 Q14.3@32.154,88.962 ; VoutV.1@70.983,77.532 80.179,77.532 80.199,77.512 R123.2@80.199,77.47
  Top Layer w0.8: C62.1@10.414,71.501 10.414,69.811 10.883,69.342 20.232,69.342 20.701,69.811 20.701,73.279 25.335,77.913 Q15.3@32.154,77.913
  other v1: 68.347,76.384 68.347,78.584 59.547,79.684 62.847,79.684 68.347,79.684 69.447,79.684 43.047,80.784 44.147,80.784 45.247,80.784 47.447,80.784 52.947,80.784 59.547,80.784 60.647,80.784 61.747,80.784 62.847,80.784 69.447,80.784 70.547,80.784 71.647,80.784 43.047,81.884 44.147,81.884 59.547,81.884 60.647,81.884 61.747,81.884 62.847,81.884 69.447,81.884 70.547,81.884 71.647,81.884 38.647,82.984 39.747,82.984 40.847,82.984 41.947,82.984 43.047,82.984 44.147,82.984 63.947,82.984 68.347,82.984 38.647,84.084 39.747,84.084 40.847,84.084 41.947,84.084 43.047,84.084 44.147,84.084 38.647,85.184 39.747,85.184 40.847,85.184 41.947,85.184 43.047,85.184 44.147,85.184 68.347,85.184 38.647,86.284 39.747,86.284 40.847,86.284 41.947,86.284 43.047,86.284 44.147,86.284 62.847,86.284 63.947,86.284 68.347,86.284 38.647,87.384 39.747,87.384 40.847,87.384 41.947,87.384 43.047,87.384 44.147,87.384 38.647,88.484 39.747,88.484 40.847,88.484 41.947,88.484 43.047,88.484 44.147,88.484 43.047,89.584 44.147,89.584 43.047,90.684 44.147,90.684 43.047,91.784 44.147,91.784
VoutW: C46.1 C48.1 pad.5@65.936,42.226 Q4.3 Q5.2 Q8.3 Q9.2 Q10.3 R20.2 R69.2 R133.2 U8.12 VoutW.1 | length 63.1
  Top Layer w0.5: U8.12@10.541,37.559 10.541,36.176 10.834,35.883 11.015,35.883 11.215,35.683 C48.1@11.215,35.433 11.049,35.267 11.049,33.531 C46.1@10.665,33.147 ; VoutW.1@70.983,38.67 71.045,38.608 73.787,38.608 74.93,39.751 80.072,39.751 80.137,39.816 80.137,49.722 R133.2@80.199,49.784
  Top Layer w0.7: C46.1@10.665,33.147 10.665,31.118 11.176,30.607 19.558,30.607 20.828,31.877 20.828,38.989 21.525,39.686 Q4.3@32.154,39.686 ; Q10.3@27.008,48.133 29.19,48.133 29.545,48.488 29.545,49.537 R69.2@29.6,49.592 30.943,49.592 31.959,50.608 Q8.3@32.154,50.608
  other v1: 68.347,37.884 63.947,40.084 68.347,40.084 58.447,41.184 59.547,41.184 60.647,41.184 61.747,41.184 62.847,41.184 69.447,41.184 70.547,41.184 71.647,41.184 40.847,42.284 41.947,42.284 43.047,42.284 44.147,42.284 47.447,42.284 52.947,42.284 56.247,42.284 57.347,42.284 58.447,42.284 59.547,42.284 60.647,42.284 61.747,42.284 62.847,42.284 69.447,42.284 70.547,42.284 71.647,42.284 38.647,43.384 44.147,43.384 58.447,43.384 59.547,43.384 62.847,43.384 68.347,43.384 69.447,43.384 68.347,44.484 68.347,46.684 38.647,48.884 44.147,48.884 38.647,49.984 39.747,49.984 43.047,49.984 44.147,49.984 43.047,51.084 44.147,51.084 43.047,52.184 44.147,52.184 43.047,53.284 44.147,53.284
Vref_pci: C27.1 CN1.B06 JP14.1 | length 88.8
  Top Layer w0.4: C27.1@79.44,12.954 79.44,11.873 79.647,11.666 79.647,11.153 CN1.B06@79.8,11
  Mid Layer 1 w0.6: CN1.B06@79.8,11 79.685,11.115 79.685,11.539 79.629,11.595 79.629,23.749 80.772,24.892 80.772,88.519 83.185,90.932 JP14.1@88.392,90.932
VU: C74.2 CN1.A25 R21.1 R116.2 VU.1 | length 214
  Top Layer w0.4: R116.2@91.886,131.318 91.886,129.478 C74.2@91.948,129.416 ; VU.1@96.428,128.27 VU.1@96.774,128.27
  Top Layer w0.5: R21.1@88.886,120.015 89.789,120.015 94.361,124.587 96.012,124.587 96.647,125.222 96.647,128.143 VU.1@96.774,128.27 v2(101.219,128.27) ; C74.2@91.948,129.416 95.282,129.416 VU.1@96.428,128.27
  Mid Layer 1 w0.4: 58.8,-5.587 CN1.A25@58.8,6.5
  Mid Layer 1 w0.5: 58.8,-5.587 61.722,-8.509 93.091,-8.509 94.361,-7.239 94.361,22.352 97.917,25.908 100.584,25.908 101.219,26.543 v2(101.219,128.27)
VV: C81.2 CN1.A26 R22.1 R127.2 VV.1 | length 157.8
  Top Layer w0.5: R22.1@89.14,67.183 89.14,68.947 90.932,70.739 95.377,70.739 96.774,72.136 VV.1@96.774,75.311 96.139,75.311 94.742,76.708 C81.2@92.075,76.708 91.956,76.708 91.886,76.778 R127.2@91.886,78.359
  Mid Layer 1 w0.4: CN1.A26@57.8,4.5 57.8,-9.921 58.039,-10.16 v2(58.674,-10.16)
  Mid Layer 2 w0.5: v2(58.674,-10.16) 88.646,-10.16 90.043,-8.763 90.043,19.431 99.949,29.337 99.949,48.768 96.774,51.943 VV.1@96.774,75.311
VW: C87.2 CN1.A27 R23.1 R134.2 VW.1 | length 122.8
  Top Layer w0.5: v2(56.769,-6.985) 91.694,-6.985 93.345,-5.334 93.345,27.178 96.774,30.607 VW.1@96.774,46.482 ; R23.1@89.521,39.751 90.551,39.751 91.821,41.021 91.821,43.18 94.858,46.217 96.509,46.217 VW.1@96.774,46.482 ; R134.2@92.013,50.419 92.013,48.649 92.083,48.579 C87.2@92.202,48.579 94.804,48.579 96.774,46.609 VW.1@96.774,46.482
  Mid Layer 1 w0.4: v2(56.769,-6.985) 56.8,-6.954 CN1.A27@56.8,6.5
W: J1.2 J3.1 Q5.3 Q9.3 Q11.3 R67.2 | length 22
  Top Layer w0.7: Q11.3@35.771,34.036 35.771,35.517 37.084,36.83 44.45,36.83 45.974,38.354 45.974,44.323 ; Q5.3@50.315,44.766 50.735,44.766 51.857,45.888 52.794,45.888 52.869,45.963 R67.2@52.869,46.036
  other v1: 46.247,55.484 47.247,55.484 48.247,55.484 52.247,55.484 53.247,55.484 54.247,55.484 55.247,55.484 56.247,55.484 56.247,56.484
  other v2: 56.896,57.912 57.785,57.912
pads on no net: CN1. CN1.A01 CN1.A02 CN1.A03 CN1.A04 CN1.A09 CN1.A10 CN1.A11 CN1.A34 CN1.A35 CN1.A36 CN1.A37 CN1.A38 CN1.A39 CN1.A40 CN1.A41 CN1.A42 CN1.A43 CN1.A44 CN1.A46 CN1.A47 CN1.A48 CN1.A50 CN1.A51 CN1.A52 CN1.A53 CN1.A54 CN1.A55 CN1.A57 CN1.A58 CN1.A59 CN1.A60 CN1.A61 CN1.A62 CN1.A63 CN1.A64 CN1.A66 CN1.A67 CN1.A68 CN1.A69 CN1.A70 CN1.A71 CN1.A72 CN1.A73 CN1.A74 CN1.A75 CN1.A77 CN1.A78 CN1.A79 CN1.A80 CN1.A81 CN1.A82 CN1.B01 CN1.B02 CN1.B03 CN1.B04 CN1.B09 CN1.B10 CN1.B11 CN1.B16 CN1.B17 CN1.B18 CN1.B25 CN1.B26 CN1.B27 CN1.B33 CN1.B34 CN1.B35 CN1.B36 CN1.B37 CN1.B38 CN1.B39 CN1.B40 CN1.B41 CN1.B42 CN1.B43 CN1.B44 CN1.B46 CN1.B47 CN1.B48 CN1.B50 CN1.B51 CN1.B52 CN1.B53 CN1.B54 CN1.B55 CN1.B57 CN1.B58 CN1.B59 CN1.B60 CN1.B61 CN1.B62 CN1.B63 CN1.B64 CN1.B66 CN1.B67 CN1.B68 CN1.B69 CN1.B70 CN1.B71 CN1.B72 CN1.B73 CN1.B74 CN1.B75 CN1.B77 CN1.B78 CN1.B79 CN1.B80 CN1.B81 CN1.B82 D13.2 D14.2 D15.2 D17.2 HW1.0 Jdummy1.1 Jdummy1.2 Jdummy2.1 Jdummy2.2 U1.6 U3.4 U4.4 U7.11 U8.11 U9.11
